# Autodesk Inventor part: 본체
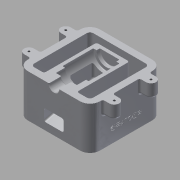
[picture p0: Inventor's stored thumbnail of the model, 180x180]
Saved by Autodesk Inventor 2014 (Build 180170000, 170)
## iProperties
Created: 2018-01
Part Number: 본체
Material: 알루미늄 6061
Document SubType Name: Modeling
Designer: user
Density: 2.71 g/cm^3
Appearance: 알루미늄 - 평지
Mass: 998.903 g
Surface Area: 834.406 cm^2
Volume: 368.599 cm^3
Author: user
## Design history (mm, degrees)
sketch "스케치1"
  geometry: L1 (-40, 55)-(40, 55); L2 (55, 40)-(55, -40); L3 (40, -55)-(-40, -55); L4 (-55, -40)-(-55, 40); L5 (40, 45)-(-40, 45); L6 (-45, 40)-(-45, -40); L7 (-40, -45)-(40, -45); L8 (45, -40)-(45, 40); A1 r 15 centre (-40, 40) between (-40, 55) and (-55, 40); A2 r 15 centre (40, 40) between (55, 40) and (40, 55); A3 r 15 centre (40, -40) between (40, -55) and (55, -40); A4 r 15 centre (-40, -40) between (-55, -40) and (-40, -55); A5 r 5 centre (-40, 40) between (-40, 45) and (-45, 40); A6 r 5 centre (-40, -40) between (-45, -40) and (-40, -45); A7 r 5 centre (40, -40) between (40, -45) and (45, -40); A8 r 5 centre (40, 40) between (45, 40) and (40, 45); 6 further points
  constraints: 16 end point, 16 point on circle, 8 centre point, 8 tangent, 6 point on line, 4 parallel, 3 equal radius, 2 midpoint, 2 perpendicular, 1 horizontal, 1 horizontal alignment, 1 vertical alignment, 7 other
  dimensions: "d0" = 110 distance of point (-55, 55) point (55, 55); "d1" = 110 distance of point (55, 55) point (55, -55); "d2" = 15 radius of A1; "d3" = 10 distance between parallel lines of L1 L5
extrude "돌출1" new body sketch "스케치1" distance "d4" = 65; taper "d5" = 0 deg
sketch "스케치2"
  geometry: L1 (-65, -20.5)-(-55, -20.5); L2 (-65, -35.5)-(-55, -35.5); L3 (-55, 40)-(-55, -40) reference; A1 r 7.5 centre (-65, -28) between (-65, -20.5) and (-65, -35.5); 1 further point
  constraints: 4 end point, 2 point on circle, 2 point on line, 2 tangent, 1 centre point, 1 horizontal, 1 parallel
  dimensions: "d6" = 15 diameter of A1; "d7" = 10 distance from line of L3 A1.centre; "d8" = 28 vertical distance of A1.centre point (0, 0)
extrude "돌출2" join sketch "스케치2" distance "d9" = 20; taper "d10" = 0 deg
hole "구멍1" diameter "d16" = 3.242; stored, may be unused: countersink angle "d20" = 90 deg, drill point angle "d22" = 118 deg; dims "d17" = 9, "d18" = 4, "d19" = 2, "d21" = 11, "d23" = 10, "d24" = 10
sketch "스케치3"
  geometry: L1 (55, 65)-(55, 0) reference; L2 (55, 0)-(45, 0) reference; L3 (45, 0)-(45, 65) reference; L4 (45, 65)-(55, 65) reference; L5 (-55, 0)-(-55, 65) reference; L6 (-55, 65)-(-45, 65) reference; L7 (-45, 65)-(-45, 0) reference; L8 (-45, 0)-(-55, 0) reference; L9 (-45, 8.564)-(35, 30); L10 (35, 30)-(35, 65); L11 (35, 65)-(-45, 65); 1 further point
  constraints: 6 end point, 2 perpendicular, 1 horizontal alignment, 1 point on line
  dimensions: "d25" = 20 distance from line of L1.start L10; "d26" = 105 deg angle of L7 L9; "d27" = 30 vertical distance of L1.end L9.end
extrude "돌출3" join sketch "스케치3" stored distance "d28" = 50; taper "d29" = 0 deg
sketch "스케치4"
  geometry: L1 (55, 65)-(55, 0) reference; L2 (55, 0)-(45, 0) reference; L3 (45, 0)-(45, 65) reference; L4 (45, 65)-(55, 65) reference; L5 (-55, 0)-(-55, 65) reference; L6 (-55, 65)-(35, 65) reference; L7 (35, 65)-(35, 30) reference; L8 (35, 30)-(-45, 8.564) reference; L9 (-45, 8.564)-(-45, 0) reference; L10 (-45, 0)-(-55, 0) reference; L11 (-55, 57.5)-(-36, 57.5); L12 (-36, 57.5)-(-36, 49); L13 (-36, 49)-(-22, 49); L14 (-22, 49)-(-22, 45); L15 (-22, 45)-(25, 45); L16 (25, 45)-(25, 50); L17 (25, 50)-(30, 50); L18 (30, 50)-(30, 65); 1 further point
  constraints: 16 end point, 5 parallel, 3 perpendicular, 2 point on line
  dimensions: "d30" = 7.5 distance between parallel lines of L6 L11; "d31" = 16 distance between parallel lines of L6 L13; "d32" = 20 distance between parallel lines of L6 L15; "d33" = 15 distance between parallel lines of L6 L17; "d34" = 19 distance of L11.start L11.end; "d35" = 14 distance of L12.end L13.end; "d36" = 47 distance of L14.end L15.end; "d37" = 5 distance of L16.end L17.end
revolve "회전1" sketch "스케치4" stored, may be unused: angle "d38" = 90 deg
sketch "스케치6"
  geometry: L1 (35, 30)-(-45, 8.564) reference; L2 (-55, 0)-(-55, 65) reference; L3 (20, 31.157)-(-55, 11.061); L4 (25, 50)-(25, 65) reference; 1 further point
  constraints: 2 end point, 1 parallel, 1 point on line
  dimensions: "d48" = 5 distance between parallel lines of L1 L3; "d68" = 5 distance from line of L3.start L4
sketch "스케치8"
  geometry: L1 (25, 29.061)-(55, 29.061); L2 (55, 29.061)-(55, 11.061); L3 (55, 11.061)-(25, 11.061); L4 (25, 11.061)-(25, 29.061); L5 (0, 0)-(80, 0) reference; 4 further points
  constraints: 8 end point, 3 midpoint, 2 parallel, 1 horizontal, 1 perpendicular, 1 vertical alignment
  dimensions: "d49" = 18 distance of L1.end L2.end; "d50" = 30 distance of L1.start L1.end
feature "스윕1" sketch "스케치6", "스케치8" dims "d51" = 0
sketch "스케치7"
  geometry: L1 (-20, -22)-(-20, 25) reference; L2 (20, -22)-(-20, -22) reference; L3 (20, 25)-(20, -22) reference; L4 (20, 25)-(-20, 25) reference; L5 (-15, 20)-(15, 20); L6 (15, 20)-(15, -17); L7 (15, -17)-(-15, -17); L8 (-15, -17)-(-15, 20); 2 further points
  constraints: 8 end point, 2 parallel, 1 horizontal, 1 midpoint, 1 perpendicular, 1 vertical alignment
  dimensions: "d43" = 5 distance between parallel lines of L4 L5; "d44" = 5 distance between parallel lines of L2 L7; "d45" = 30 distance between parallel lines of L6 L8
extrude "돌출5" cut sketch "스케치7" stored distance "d52" = 35; taper "d53" = 0 deg
fillet "모깎기1" dims "d54" = 1
fillet "모깎기11" dims "d67" = 3
fillet "모깎기2" dims "d55" = 3
chamfer "모따기1" distance "d56" = 1; stored, may be unused: second distance "d57" = 2, angle "d58" = 45 deg
fillet "모깎기3" dims "d59" = 3
fillet "모깎기4" dims "d60" = 3
fillet "모깎기12" dims "d73" = 3
fillet "모깎기5" dims "d61" = 3
fillet "모깎기7" dims "d63" = 3
sketch "스케치9"
  geometry: L1 (0, -15)-(-65, -15) reference; 2 further points
  constraints: 1 other
  dimensions: "d69" = 20 distance of point (0, 40) point (-20, 40); "d70" = 55 distance from line of L1 point (-20, 40)
feature "엠보싱1" sketch "스케치9" dims "d0" = 110, "d1" = 110, "d2" = 15, "d3" = 10, "d71" = 0.5, "d72" = 0
node "솔리드1"
pattern_linear "직사각형 패턴1" dims "d13" = 56
mirror "대칭1"
node "투영된 루프2"
node "절단 모서리 투영1"
node "절단 모서리 투영2"
